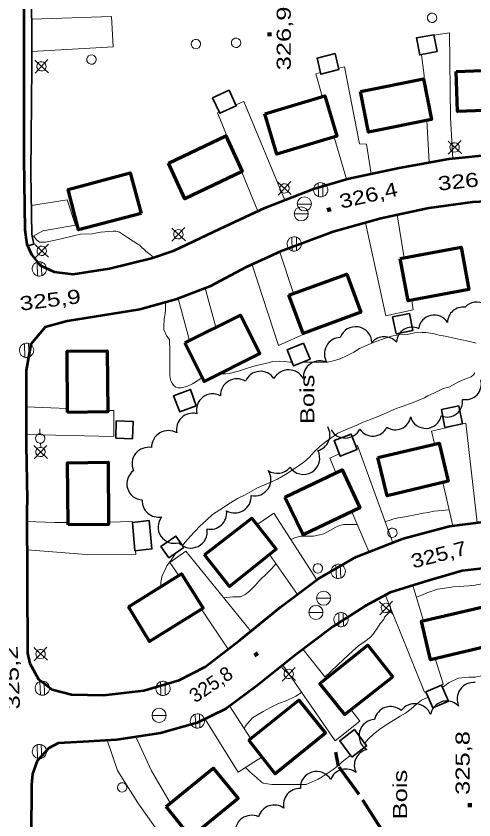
# Model space of a CAD drawing. Extents: x 240591 to 242335, y 5323482 to 5326937.
# Drawn here: x 241042.3 to 241139.6, y 5325255.9 to 5325426.8 of the extents above; entities that cross this region are included whole.
import ezdxf
from ezdxf.enums import TextEntityAlignment as Align

# ---------------------------------------------------------------- set-up
doc = ezdxf.new("R2010")
doc.units = 0
doc.header["$LTSCALE"] = 1.2
doc.linetypes.add('LONG_DASHED', pattern=[7.5, 6, -1.5])
for name, color, linetype, lineweight in [('19', 7, 'Continuous', 13), ('2', 7, 'Continuous', 13), ('21', 7, 'Continuous', 53), ('22', 7, 'LONG_DASHED', 70), ('3', 7, 'Continuous', 140), ('31', 7, 'Continuous', 70), ('36', 7, 'Continuous', 13), ('44', 7, 'Continuous', 25)]:
    doc.layers.add(name, color=color, linetype=linetype, lineweight=lineweight)

msp = doc.modelspace()

# ---------------------------------------------------------------- linework, layer by layer
at = {"layer": '19'}
for p, q in [((241130.1, 5325395.6), (241129.6, 5325404.6)), ((241112.5, 5325392.1), (241109.9, 5325401)), ((241093.7, 5325385.3), (241090.3, 5325393.6)), ((241124.8, 5325375.4), (241123.3, 5325384.5)), ((241101.3, 5325367.8), (241098.4, 5325376.6)), ((241082.5, 5325368.9), (241084.8, 5325360.6)), ((241076.8, 5325366.7), (241079.2, 5325357.8)), ((241053.3, 5325343.3), (241044.5, 5325343.7)), ((241133, 5325327.6), (241135.1, 5325318.4)), ((241113.7, 5325321.4), (241117.3, 5325312.9)), ((241096.2, 5325312.3), (241102.1, 5325303.8)), ((241126.6, 5325305.7), (241128.9, 5325298.2)), ((241081.8, 5325300.5), (241087.4, 5325292.2)), ((241103.3, 5325292.1), (241108.2, 5325285.9)), ((241087.7, 5325280.1), (241092.2, 5325273.1))]:
    msp.add_line(p, q, dxfattribs=at)
for points in [[(241045.7, 5325419.2), (241063, 5325420.2), (241062.6, 5325426.7), (241045.7, 5325426.1)], [(241131.1, 5325422.7), (241134.4, 5325423.2), (241134.6, 5325405.1), (241135.1, 5325396.4)], [(241129.1, 5325412.3), (241129, 5325414.1), (241128.5, 5325418.5)], [(241110.9, 5325415.7), (241112.1, 5325416), (241115.3, 5325399.6), (241116.8, 5325399.5), (241117.8, 5325393.2)], [(241107.4, 5325409.7), (241106, 5325414.5), (241107, 5325414.8)], [(241089, 5325407.9), (241090.7, 5325408.6), (241099.4, 5325387.6)], [(241088.9, 5325397), (241085.1, 5325406.2), (241085.5, 5325406.3)], [(241045.6, 5325386.5), (241053.2, 5325387.7), (241055, 5325382.3), (241048, 5325381.1), (241045.8, 5325379.9)], [(241116.6, 5325382.8), (241120.9, 5325363), (241126.7, 5325364.3), (241126.4, 5325366.3)], [(241092.5, 5325373.9), (241098.1, 5325356.7), (241104.1, 5325359.4), (241104.1, 5325359.5)], [(241044.5, 5325337.8), (241063.1, 5325337.4), (241063.1, 5325342.9), (241061.8, 5325342.9)], [(241140.3, 5325319.1), (241137.9, 5325340.2), (241130.6, 5325338.5), (241131.2, 5325335.8)], [(241122.4, 5325314.8), (241114.9, 5325335.5), (241114.5, 5325335.3)], [(241111, 5325333.7), (241109, 5325332.8), (241110.3, 5325329.7)], [(241106.2, 5325306.9), (241097.1, 5325321.1), (241093.5, 5325318.6)], [(241053.4, 5325319.1), (241050.6, 5325319.1), (241044.6, 5325319.3)], [(241067.1, 5325319.1), (241067.1, 5325319.3), (241062, 5325319.2)], [(241044.7, 5325313.3), (241056.4, 5325312.4), (241067.8, 5325312.3), (241067.7, 5325313.1)], [(241092.2, 5325296), (241078.4, 5325313), (241075, 5325310.6), (241076.9, 5325307.8)], [(241129.4, 5325283.1), (241129.1, 5325283), (241120.8, 5325303.6)], [(241113.5, 5325279.3), (241115.4, 5325276.9), (241110.1, 5325272.7), (241099, 5325288.8)], [(241131.4, 5325290.2), (241133.1, 5325284.8), (241132.7, 5325284.5)], [(241094.6, 5325269.3), (241089.5, 5325266), (241082.5, 5325277.3)], [(241067.8, 5325273.5), (241071.1, 5325266.3), (241075.1, 5325259.5)], [(241079.8, 5325252.5), (241081.2, 5325250.6), (241076.9, 5325247.2), (241068.2, 5325259.5), (241063.9, 5325266.4), (241061.7, 5325272.8)]]:
    msp.add_lwpolyline(points, dxfattribs=at)
at = {"layer": '2'}
for points in [[(241071.5, 5325375.4), (241071.2, 5325375.8), (241070.8, 5325376.1), (241069.9, 5325376.8), (241068.6, 5325378), (241068.2, 5325378.3), (241067.2, 5325378.9), (241066, 5325379.7), (241064.3, 5325380.8), (241063.5, 5325381), (241063, 5325381), (241060.3, 5325380.8), (241059.2, 5325380.6), (241058.6, 5325380.5), (241056, 5325380.4), (241054.8, 5325380.1), (241052.2, 5325379.5), (241050, 5325379), (241048.6, 5325378.7), (241047.3, 5325378.7), (241046.7, 5325379.2), (241046.3, 5325379.7), (241046.1, 5325380)], [(241075.8, 5325348.3), (241075.5, 5325348.7), (241075.2, 5325349.2), (241075.1, 5325349.8), (241075, 5325350.5), (241075, 5325352.7), (241075, 5325355.5), (241074.9, 5325358), (241074.4, 5325358.7), (241073.7, 5325360.1), (241073.7, 5325360.7), (241073.8, 5325362.4), (241074, 5325363.5), (241074.1, 5325364.3), (241074.1, 5325365.9)], [(241140.1, 5325357.2), (241139.5, 5325357.4), (241139, 5325357.5), (241136.4, 5325358.1), (241133.5, 5325358.7), (241132.2, 5325358.9), (241130.9, 5325359.3), (241129.4, 5325359.5), (241128.6, 5325359.5), (241127, 5325359.4), (241125.4, 5325359.1), (241123.6, 5325359), (241122.1, 5325358.7), (241120.8, 5325358.3), (241118.8, 5325357.6), (241117.4, 5325357), (241115.3, 5325356.1), (241114.1, 5325355.3), (241112.7, 5325354.6), (241111.2, 5325353.9), (241109.8, 5325353.5), (241108.4, 5325353.2), (241107.2, 5325353.2), (241106, 5325353.2), (241103.3, 5325353.2)], [(241101, 5325353.2), (241100.5, 5325353.2), (241099.4, 5325353.3), (241098.2, 5325353.4), (241096.9, 5325353.3), (241095.6, 5325353), (241093.1, 5325352.4), (241091.5, 5325351.9), (241089.6, 5325351.3), (241087.6, 5325350.8), (241086.9, 5325350.7), (241085.5, 5325350.7)], [(241077.7, 5325314.3), (241077.9, 5325314.5), (241079.3, 5325316.1), (241081.4, 5325318.3), (241082.8, 5325319.6), (241084.1, 5325320.8), (241085.6, 5325321.8), (241087.9, 5325323.3), (241089.4, 5325324.2), (241091, 5325325), (241093.5, 5325326.4), (241094.5, 5325326.8), (241097.9, 5325328.3), (241099.6, 5325329.3), (241101.2, 5325330.4), (241103.5, 5325331.9), (241104.7, 5325333), (241105.7, 5325334.1), (241106.8, 5325335.2), (241108, 5325336.2), (241109.4, 5325337.2), (241110.7, 5325338.1), (241112.3, 5325338.8), (241114.7, 5325339.8), (241116.1, 5325340.4), (241117.6, 5325341), (241119.9, 5325341.9), (241121, 5325342.4), (241123.1, 5325343.3), (241124.6, 5325343.8), (241126.7, 5325344.6), (241129.1, 5325345.6), (241129.8, 5325346), (241131.2, 5325346.7), (241133.1, 5325347.6), (241134.3, 5325347.9), (241135.2, 5325348.4), (241136.5, 5325349.1), (241138, 5325349.7), (241139, 5325350.1), (241139.5, 5325350.5), (241139.8, 5325350.9)], [(241081.9, 5325349.9), (241081.4, 5325349.6), (241079.8, 5325348.6), (241078.6, 5325348), (241077.4, 5325347.7), (241076.8, 5325347.7), (241076.3, 5325347.9), (241075.8, 5325348.3)], [(241134.3, 5325321.8), (241133.6, 5325321.7), (241131.1, 5325321.5), (241129.9, 5325321.2), (241128.8, 5325321.1), (241127.8, 5325320.9), (241124.9, 5325320.3), (241123.6, 5325320.1), (241122.6, 5325319.9), (241121.6, 5325319.5), (241120.8, 5325319.3)], [(241114.9, 5325318.7), (241111.9, 5325318.7), (241110.9, 5325318.4), (241110.3, 5325318.1), (241107.7, 5325316.7), (241106.5, 5325316.4), (241105.5, 5325316.2), (241104.3, 5325316.2), (241102.8, 5325316.2), (241101.7, 5325315.9), (241100.7, 5325315.5)], [(241073.2, 5325305.5), (241073.1, 5325305.7), (241073.1, 5325306.4), (241073.4, 5325307.8), (241073.7, 5325308.5), (241074.4, 5325309.9), (241075.4, 5325311.3), (241076.2, 5325312.5)], [(241097.5, 5325310.3), (241096.7, 5325309.3), (241095.8, 5325308.5), (241093.9, 5325306.6), (241093.2, 5325305.8), (241091.9, 5325304.5), (241091, 5325303.8), (241090, 5325303.3), (241089.5, 5325303.3), (241088.4, 5325303.3), (241086.5, 5325303.1)], [(241127.4, 5325303.2), (241128.3, 5325303.6), (241129.8, 5325304.2), (241131.9, 5325304.9), (241133, 5325305.1), (241135.2, 5325305.4), (241136.5, 5325305.5), (241139.5, 5325305.7), (241140.5, 5325305.9), (241142.3, 5325306.2), (241145.6, 5325306.8)], [(241107.9, 5325286.3), (241108.7, 5325286.9), (241109.3, 5325287.5), (241110.6, 5325288.8), (241111.9, 5325290), (241113.9, 5325291.8), (241115.1, 5325292.9), (241116.4, 5325293.8), (241117.6, 5325294.7), (241118.1, 5325295.3), (241119, 5325296.5), (241119.7, 5325297.6), (241120.5, 5325298.5), (241120.6, 5325299), (241121, 5325299.4), (241122.1, 5325300.4)], [(241142.6, 5325286.8), (241139.9, 5325286.2), (241138.5, 5325286.2), (241136.3, 5325286), (241135.8, 5325285.8), (241134.2, 5325285), (241133.7, 5325284.6), (241132.9, 5325284.1)], [(241090.8, 5325275.2), (241091, 5325275.7), (241091.5, 5325276.4), (241092.6, 5325277.6), (241093.3, 5325278), (241094.8, 5325278.9), (241096.4, 5325279.8), (241098.1, 5325280.6), (241099.7, 5325281.2), (241101.8, 5325282.2), (241103.1, 5325283)], [(241129.9, 5325282), (241128.5, 5325281.3), (241127.4, 5325280.5), (241126.3, 5325279.5), (241125.1, 5325278.6), (241123.9, 5325277.9), (241121.3, 5325276.3), (241119.7, 5325275.2), (241118.2, 5325274), (241117.2, 5325273.1), (241116.4, 5325272.2)], [(241113.4, 5325269.6), (241113.2, 5325269.4), (241111.6, 5325268.2), (241110.6, 5325267.3), (241109.7, 5325266.6), (241107.4, 5325265), (241106.5, 5325264.5), (241104, 5325263.4), (241103.5, 5325263.4), (241102.4, 5325263.4), (241099.4, 5325263.4), (241096.7, 5325263.4), (241094.8, 5325263.7), (241094.4, 5325264), (241093.5, 5325264.8), (241092, 5325266.1), (241091.1, 5325267)]]:
    msp.add_lwpolyline(points, dxfattribs=at)
at = {"layer": '21'}
for points in [[(241044, 5325433.2), (241044, 5325396.4), (241044.2, 5325381.3), (241044.6, 5325378.3), (241045.6, 5325376.1), (241047.4, 5325373.8), (241050.4, 5325372.4), (241054.5, 5325371.9), (241062.2, 5325373.1), (241071.1, 5325375.3), (241075.9, 5325376.9), (241085.6, 5325381.5), (241095.2, 5325386), (241105.5, 5325390), (241113, 5325392.2), (241123.7, 5325394.5), (241134.3, 5325396.4), (241144.1, 5325397.4)], [(241149.7, 5325387.7), (241139.3, 5325387.2), (241130, 5325385.9), (241119.8, 5325383.7), (241109.7, 5325380.9), (241098.5, 5325376.7), (241091.2, 5325373.4), (241083.5, 5325369.3), (241076.3, 5325366.5), (241068.6, 5325364.4), (241061.1, 5325363.2), (241053.2, 5325361.9), (241048.5, 5325360.6), (241045.5, 5325357), (241044.5, 5325351.4), (241044.5, 5325335.6), (241044.7, 5325324), (241044.6, 5325321.8), (241044.8, 5325291.3), (241045.3, 5325289.1), (241047.1, 5325285.8), (241050, 5325283.6), (241054.1, 5325282.5), (241060.9, 5325282.4), (241069.5, 5325283.4), (241077, 5325285.6), (241082.5, 5325288.4), (241089.9, 5325294.1), (241098.6, 5325301.2), (241106.5, 5325307.1), (241114.6, 5325311.8), (241124.6, 5325315.7), (241134.4, 5325318.3), (241142.8, 5325319.4)], [(241144.6, 5325309.7), (241137.1, 5325308.8), (241129.8, 5325306.7), (241121.8, 5325304.2), (241116.6, 5325301.4), (241109.7, 5325297), (241101.6, 5325290.9), (241093.5, 5325284.4), (241086.9, 5325279.5), (241080.8, 5325276.5), (241073, 5325274.3), (241063.7, 5325272.9), (241056.6, 5325272.5), (241051.3, 5325272.2), (241049.3, 5325271.1), (241046.8, 5325268.4), (241045.8, 5325265.7), (241045.6, 5325263.3), (241045.5, 5325241.6)]]:
    msp.add_lwpolyline(points, dxfattribs=at)
at = {"layer": '22', "linetype": 'Continuous', "lineweight": 35}
msp.add_lwpolyline([(241050.5, 5325448.5), (241050.6, 5325446.8), (241048, 5325445.4), (241046.6, 5325443.6), (241045.8, 5325441.6), (241045.6, 5325436.8), (241045.7, 5325416), (241045.5, 5325393.4), (241045.7, 5325380.3), (241046.1, 5325378.3), (241044.8, 5325377.9), (241044.8, 5325377.9)], dxfattribs=at)
at = {"layer": '22'}
msp.add_lwpolyline([(241158.6, 5325234.6), (241149.7, 5325236.5), (241140.3, 5325238.4), (241130.8, 5325241.7), (241125.3, 5325245.9), (241119.9, 5325254), (241115.2, 5325261.3), (241110.8, 5325267.3), (241110.3, 5325270.3)], dxfattribs=at)
at = {"layer": '3'}
for p, q in [((241096.2, 5325422.5), (241096.2, 5325423.3)), ((241108.4, 5325385.5), (241109.2, 5325385.7)), ((241093, 5325290.8), (241093.7, 5325291.3)), ((241138.7, 5325258.6), (241138.7, 5325259.4))]:
    msp.add_line(p, q, dxfattribs=at)
at = {"layer": '31', "lineweight": 35}
for points in [[(241131.8, 5325419.2), (241128.1, 5325418.5), (241127.4, 5325422.1), (241131.1, 5325422.8)], [(241110.9, 5325415.4), (241107.1, 5325414.4), (241106.3, 5325417.8), (241110.1, 5325418.8)], [(241084.1, 5325409.4), (241087.6, 5325411), (241089.1, 5325407.7), (241085.6, 5325406.1)], [(241122.3, 5325362.8), (241125.9, 5325363.5), (241126.6, 5325359.9), (241123.1, 5325359.2)], [(241103.4, 5325357.2), (241104.8, 5325353.8), (241101.3, 5325352.4), (241099.9, 5325355.8)], [(241080.6, 5325343.9), (241077.1, 5325342.6), (241075.8, 5325346), (241079.4, 5325347.4)], [(241136.4, 5325343.9), (241137.2, 5325340.1), (241133.4, 5325339.3), (241132.7, 5325343.1)], [(241063.5, 5325337), (241063.6, 5325340.7), (241067.2, 5325340.6), (241067.1, 5325336.9)], [(241114.8, 5325334.6), (241111.2, 5325333.2), (241109.9, 5325336.5), (241113.5, 5325337.9)], [(241070.6, 5325319.5), (241071.2, 5325313.5), (241067.6, 5325313.1), (241067.1, 5325319.1)], [(241078, 5325313.8), (241074.8, 5325311.6), (241073.1, 5325314), (241076.3, 5325316.2)], [(241134.2, 5325281.1), (241130.9, 5325279.7), (241129.4, 5325283.1), (241132.7, 5325284.5)], [(241113.7, 5325269.2), (241111.1, 5325272.7), (241114.2, 5325275.1), (241116.8, 5325271.6)]]:
    msp.add_lwpolyline(points, close=True, dxfattribs=at)
at = {"layer": '31'}
for points in [[(241135.8, 5325415), (241149.1, 5325415.5), (241149.4, 5325407), (241136.1, 5325406.5)], [(241115.5, 5325410.7), (241128.9, 5325413.4), (241130.6, 5325404.8), (241117.2, 5325402.1)], [(241095.2, 5325406), (241107.9, 5325409.8), (241110.5, 5325401.2), (241097.7, 5325397.4)], [(241074.7, 5325395.5), (241086.9, 5325401.3), (241090.4, 5325393.7), (241078.2, 5325387.9)], [(241068.9, 5325384.8), (241055.6, 5325381.3), (241053.4, 5325389.9), (241066.6, 5325393.4)], [(241123.9, 5325375.2), (241136.9, 5325377.6), (241138.5, 5325368.6), (241125.6, 5325366.2)], [(241100.3, 5325367.4), (241112.6, 5325371.9), (241115.6, 5325363.8), (241103.3, 5325359.3)], [(241078.2, 5325357.3), (241090, 5325363.2), (241094.1, 5325355), (241082.3, 5325349.1)], [(241053.3, 5325342.5), (241053.2, 5325355.5), (241061.7, 5325355.6), (241061.8, 5325342.6)], [(241119.2, 5325332.9), (241132.2, 5325336), (241134.1, 5325327.9), (241121.2, 5325324.8)], [(241053.4, 5325318.6), (241053.3, 5325331.8), (241061.9, 5325331.9), (241062, 5325318.7)], [(241099.4, 5325324.5), (241111.6, 5325330.3), (241115.4, 5325322.2), (241103.3, 5325316.5)], [(241082.4, 5325312.2), (241092.4, 5325320), (241097.6, 5325313.4), (241087.7, 5325305.5)], [(241066.2, 5325301.2), (241077.5, 5325308.2), (241082.1, 5325300.9), (241070.7, 5325293.8)], [(241143.5, 5325293), (241130.4, 5325289.9), (241128.5, 5325298.1), (241141.6, 5325301.2)], [(241122.4, 5325286.3), (241112.2, 5325278.3), (241106.9, 5325284.9), (241117.1, 5325293)], [(241091.8, 5325272.8), (241102.4, 5325281.3), (241108.1, 5325274.3), (241097.4, 5325265.7)], [(241074.2, 5325258.7), (241084.2, 5325266.9), (241089.5, 5325260.4), (241079.5, 5325252.2)]]:
    msp.add_lwpolyline(points, close=True, dxfattribs=at)
at = {"layer": '36'}
for p, q in [((241049.2, 5325414.7), (241046.3, 5325417.4)), ((241046.4, 5325414.6), (241049.1, 5325417.5)), ((241134.1, 5325397.4), (241136.9, 5325400.3)), ((241137, 5325397.5), (241134.1, 5325400.2)), ((241100.8, 5325388.8), (241097.9, 5325391.5)), ((241098, 5325388.7), (241100.7, 5325391.6)), ((241106.5, 5325391.3), (241106.6, 5325388.4)), ((241107.5, 5325388.4), (241107.5, 5325391.3)), ((241102.1, 5325386.8), (241105.1, 5325386.8)), ((241101.4, 5325384.7), (241104.4, 5325384.7)), ((241075.4, 5325378.9), (241078.2, 5325381.8)), ((241078.3, 5325379), (241075.4, 5325381.7)), ((241100.9, 5325379.7), (241101, 5325376.8)), ((241101.9, 5325376.9), (241101.9, 5325379.8)), ((241049.2, 5325375.5), (241046.3, 5325378.2)), ((241046.4, 5325375.4), (241049.2, 5325378.3)), ((241046.8, 5325374.4), (241046.9, 5325371.5)), ((241047.8, 5325371.6), (241047.7, 5325374.5)), ((241044.1, 5325357.1), (241044.2, 5325354.2)), ((241045.1, 5325354.3), (241045, 5325357.2)), ((241047.4, 5325339), (241047.4, 5325338)), ((241049, 5325332.7), (241046.1, 5325335.5)), ((241046.2, 5325332.6), (241048.9, 5325335.5)), ((241047.6, 5325335), (241047.5, 5325336)), ((241110.3, 5325310.1), (241110.4, 5325307.2)), ((241111.3, 5325307.3), (241111.2, 5325310.2)), ((241106.2, 5325303), (241109.2, 5325303)), ((241119.6, 5325299.5), (241122.3, 5325302.4)), ((241122.4, 5325299.6), (241119.5, 5325302.3)), ((241104.5, 5325300), (241107.5, 5325300)), ((241110.9, 5325299.9), (241110.9, 5325297)), ((241111.9, 5325297), (241111.8, 5325299.9)), ((241049, 5325289.8), (241046.1, 5325292.5)), ((241046.2, 5325289.7), (241048.9, 5325292.6)), ((241101.7, 5325285.5), (241098.8, 5325288.3)), ((241098.9, 5325285.4), (241101.6, 5325288.3)), ((241047.4, 5325285.3), (241047.5, 5325282.4)), ((241048.4, 5325282.5), (241048.3, 5325285.4)), ((241073, 5325285.3), (241073.1, 5325282.4)), ((241074, 5325282.4), (241074, 5325285.3)), ((241071.2, 5325278.1), (241074.2, 5325278.1)), ((241080.4, 5325278.3), (241080.5, 5325275.4)), ((241081.4, 5325275.5), (241081.3, 5325278.4)), ((241046.8, 5325271.8), (241046.9, 5325268.9)), ((241047.8, 5325269), (241047.7, 5325271.9))]:
    msp.add_line(p, q, dxfattribs=at)
for centre in [(241103.579, 5325386.842), (241102.909, 5325384.712), (241107.669, 5325303.012), (241106.039, 5325299.992), (241072.719, 5325278.102)]:
    msp.add_circle(centre, 1.5, dxfattribs=at)
for centre, major_axis in [((241130.713, 5325426.39), (0.261, -0.965)), ((241089.073, 5325421.07), (0.261, -0.965)), ((241080.543, 5325420.82), (0.261, -0.965)), ((241058.373, 5325417.51), (0.261, -0.965)), ((241047.734, 5325416.077), (-0.261, 0.965)), ((241135.504, 5325398.847), (-0.261, 0.965)), ((241099.364, 5325390.127), (-0.261, 0.965)), ((241107.034, 5325389.837), (-0.396, 1.465)), ((241076.814, 5325380.377), (-0.261, 0.965)), ((241101.434, 5325378.317), (-0.396, 1.465)), ((241047.784, 5325376.847), (-0.261, 0.965)), ((241047.294, 5325372.997), (-0.396, 1.465)), ((241044.574, 5325355.707), (-0.396, 1.465)), ((241047.471, 5325336.959), (-0.261, 0.965)), ((241047.524, 5325334.097), (-0.261, 0.965)), ((241122.273, 5325316.92), (0.261, -0.965)), ((241106.443, 5325309.35), (0.261, -0.965)), ((241110.774, 5325308.707), (-0.396, 1.465)), ((241120.924, 5325300.937), (-0.261, 0.965)), ((241111.364, 5325298.447), (-0.396, 1.465)), ((241047.554, 5325291.137), (-0.261, 0.965)), ((241100.264, 5325286.897), (-0.261, 0.965)), ((241047.904, 5325283.887), (-0.396, 1.465)), ((241073.544, 5325283.837), (-0.396, 1.465)), ((241080.874, 5325276.907), (-0.396, 1.465)), ((241047.304, 5325270.407), (-0.396, 1.465)), ((241064.863, 5325262.79), (0.261, -0.965))]:
    msp.add_ellipse(centre, major_axis=major_axis, ratio=0.99964, dxfattribs=at)
at = {"layer": '44'}
for centre, radius, start, end in [((241140.187, 5325362.629), 3.331, 339.64542, 137.62276), ((241137.322, 5325361.565), 3.333, 83.02486, 178.83165), ((241131.158, 5325359.88), 3.33, 31.76143, 172.67139), ((241114.468, 5325357.251), 3.472, 2.44573, 160.10203), ((241126.476, 5325357.271), 3.334, 65.57621, 176.91632), ((241111.319, 5325354.964), 3.471, 91.90353, 212.16436), ((241120.565, 5325355.128), 3.473, 41.96982, 139.16462), ((241106.842, 5325350.008), 3.467, 63.65876, 185.43503), ((241094.255, 5325347.763), 3.483, 34.38457, 156.53172), ((241100.246, 5325347.972), 3.578, 28.50828, 150.57646), ((241137.844, 5325348.549), 3.337, 258.56845, 15.48763), ((241084.103, 5325342.963), 3.467, 61.83589, 192.17113), ((241133.87, 5325344.854), 3.34, 248.71131, 7.29632), ((241079.876, 5325338.869), 3.466, 76.01683, 192.30702), ((241129.39, 5325342.453), 3.344, 196.01733, 347.72691), ((241122.901, 5325342.127), 3.329, 236.8463, 349.66687), ((241074.673, 5325335.076), 3.553, 59.24664, 180.90735), ((241112.276, 5325340.527), 3.477, 210.15864, 333.21624), ((241070.456, 5325331.617), 3.467, 78.96518, 204.83963), ((241069.337, 5325327.347), 3.467, 125.75868, 266.74785), ((241093.017, 5325328.228), 3.465, 257.89775, 33.64859), ((241097.835, 5325333.027), 3.468, 236.10667, 321.16023), ((241088.765, 5325324.66), 3.53, 241.11244, 2.91801), ((241072.607, 5325323.704), 3.472, 177.00812, 280.96192), ((241083.627, 5325321.113), 3.463, 258.03616, 7.58039), ((241075.971, 5325318.133), 3.462, 141.34807, 286.01475), ((241079.488, 5325317.146), 3.47, 222.40506, 9.61819), ((241127.031, 5325276.965), 3.61, 21.02153, 142.94934)]:
    msp.add_arc(centre, radius, start, end, dxfattribs=at)
for centre, major_axis, ratio, start_param, end_param in [((241089.27, 5325346.106), (-1.716, -3.086), 0.999995, 3.1173378, 5.2441953), ((241105.541, 5325337.721), (2.848, -1.991), 0.997634, 5.5869723, 7.402808), ((241118.125, 5325340.728), (2.697, 1.84), 0.999994, 3.1148619, 5.2453037), ((241103.381, 5325332.795), (1.815, -2.955), 0.999565, 4.7411335, 7.7970568), ((241139.49, 5325281.613), (-1.99, -2.833), 0.99994, 3.6352445, 5.7895335), ((241121.89, 5325276.523), (-3.229, -1.237), 0.99994, 3.6343055, 5.7139059), ((241133.809, 5325277.697), (-3.27, -1.116), 0.99994, 3.6343175, 5.7904605), ((241118.645, 5325273.77), (-0.562, -3.409), 0.999985, 3.3459295, 5.8913404), ((241117.648, 5325267.478), (-1.183, -3.244), 0.999985, 3.7319845, 5.5302005), ((241106.177, 5325262.711), (-3.431, -0.386), 0.99994, 3.556855, 6.2208148), ((241112.398, 5325263.24), (-3.373, -0.748), 0.99994, 3.8128553, 5.7076355), ((241102.603, 5325259.104), (-2.424, -2.465), 0.999985, 3.8832641, 5.7085524), ((241097.171, 5325255.573), (-1.691, -3.017), 0.999962, 3.0152104, 4.9398702), ((241092.385, 5325253.325), (-1.392, -3.247), 0.999995, 3.1188882, 5.2435801)]:
    msp.add_ellipse(centre, major_axis=major_axis, ratio=ratio, start_param=start_param, end_param=end_param, dxfattribs=at)

# ---------------------------------------------------------------- texts
at = {"layer": '3', "width": 1.35}
msp.add_text('326,9', height=3, rotation=90, dxfattribs=at).set_placement((241100.7, 5325422), align=Align.CENTER)
at = {"layer": '3'}
for s, rotation, width, p in [('326,3', 6.207, 1.3, (241145.076, 5325391.044)), ('325,7', 14.663, 1.2, (241138.341, 5325312.351))]:
    msp.add_text(s, height=3, rotation=rotation, dxfattribs=dict(at, width=width)).set_placement(p, align=Align.RIGHT)
for s, rotation, width, p in [('326,4', 12.767, 1.25, (241111.4, 5325385.8)), ('325,9', 7.295, 1.3, (241043.3, 5325364.1)), ('325,2', 92.265, 1.35, (241043.2, 5325279.4)), ('325,8', 90, 1.35, (241138.7, 5325261.2))]:
    msp.add_text(s, height=3, rotation=rotation, dxfattribs=dict(at, width=width)).set_placement(p)
msp.add_text('325,8', height=3, rotation=34.057, dxfattribs=at).set_placement((241088.72, 5325286.256), align=Align.RIGHT)
at = {"layer": '44', "width": 1.35}
for p in [(241105.7, 5325340), (241125.4, 5325256)]:
    msp.add_text('Bois', height=3, rotation=90, dxfattribs=at).set_placement(p)

doc.saveas('drawing.dxf')
